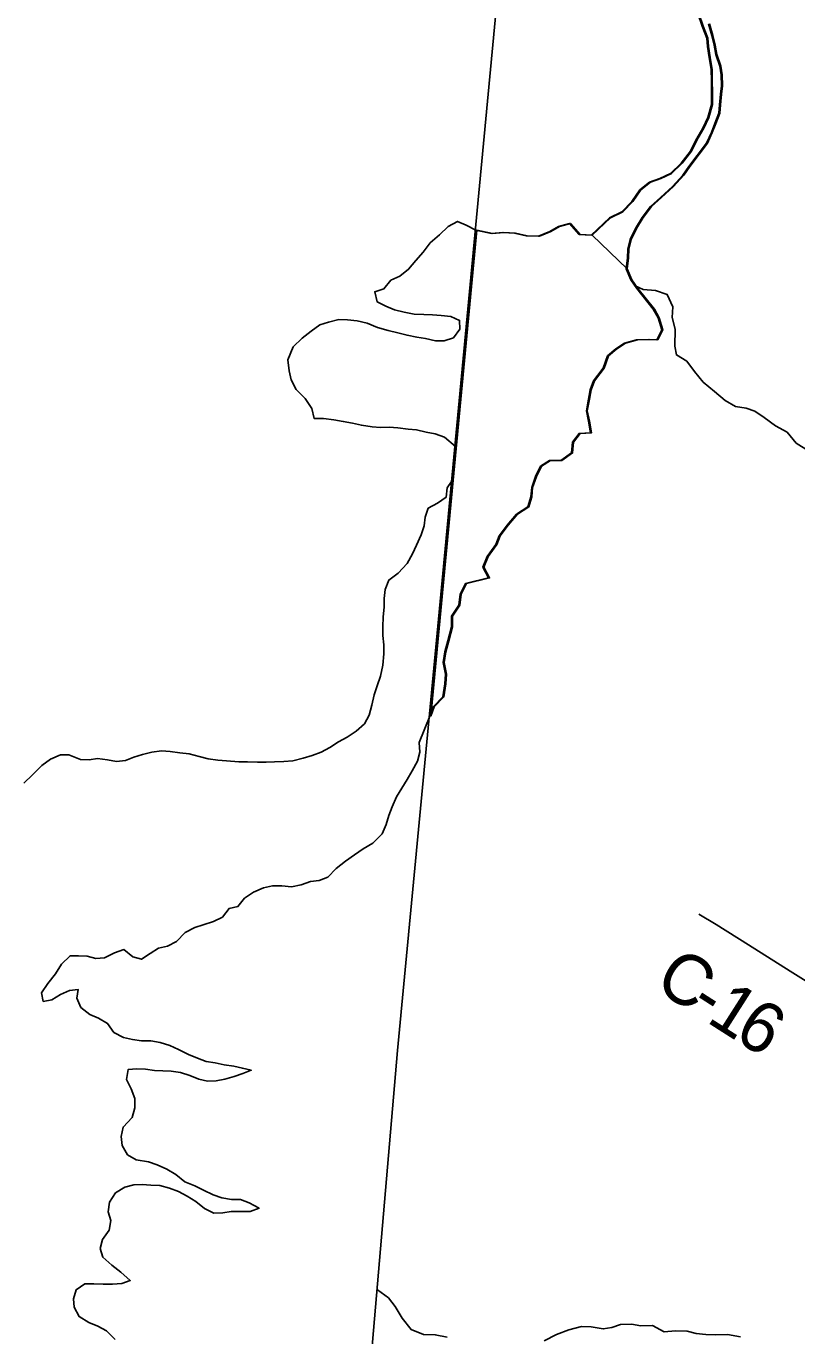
# Model space of a CAD drawing. Extents: x 1442749 to 1756758, y 235267 to 677782.
# Drawn here: x 1548844 to 1553409, y 561298 to 569056 of the extents above; entities that cross this region are included whole.
import ezdxf

# ---------------------------------------------------------------- set-up
doc = ezdxf.new("R2010")
doc.units = 0
for name, color, linetype in [('GM_X_Adjacent_County', 7, 'Continuous'), ('GM_X_County', 7, 'Continuous'), ('GM_X_County_Road', 7, 'Continuous'), ('GM_X_County_Road_Text', 7, 'Continuous'), ('GM_X_Major_Lake', 7, 'Continuous'), ('GM_X_Major_River', 7, 'Continuous'), ('GM_X_Minor_River', 7, 'Continuous'), ('GM_X_Township', 7, 'Continuous')]:
    doc.layers.add(name, color=color, linetype=linetype)

msp = doc.modelspace()

# ---------------------------------------------------------------- linework, layer by layer
at = {"layer": 'GM_X_Adjacent_County'}
msp.add_lwpolyline([(1510501.5, 579143.6), (1513514.2, 578839.9), (1514569.4, 578743.8), (1516950, 578526.9), (1518829.2, 578331.8), (1524308.5, 577745.2), (1526680.1, 577523.9), (1529626.7, 577249.2), (1531676.6, 577058.1), (1536645.4, 576561.3), (1543156.7, 575957.6), (1545678.1, 575724.5), (1546403.2, 575641.6), (1549246.3, 575316.8), (1549693.5, 575265.7), (1552179.9, 574981.5), (1551567.1, 568507.3), (1551312.1, 565815), (1551044.2, 562987.6), (1549909.5, 549764.5)], dxfattribs=at)
at = {"layer": 'GM_X_County'}
msp.add_lwpolyline([(1549909.5, 549764.5), (1551044.2, 562987.6), (1551312.1, 565815), (1551567.1, 568507.3), (1552179.9, 574981.5), (1554998.6, 574736.4), (1559309.5, 574361.4), (1567480, 573617.6), (1572928.5, 573040.3)], dxfattribs=at)
at = {"layer": 'GM_X_County_Road'}
msp.add_lwpolyline([(1552829.3, 563796.3), (1552931.1, 563735.8), (1553122.5, 563615.3), (1553368.7, 563458.6), (1553713.5, 563242.7), (1553882.9, 563136.1), (1554050, 563032.1), (1554178.3, 562952.7), (1554281.9, 562889.8)], dxfattribs=at)
at = {"layer": 'GM_X_Major_Lake'}
for p, q in [((1551235, 564969.3), (1551507.7, 567847.8)), ((1551513.6, 567847.8), (1551240.9, 564969.3)), ((1551386.4, 566567.3), (1551507.7, 567847.8)), ((1552403.3, 567618.9), (1552196.8, 567817.5)), ((1551235, 564969.3), (1551367.3, 566365.7))]:
    msp.add_line(p, q, dxfattribs=at)
for points in [[(1551507.7, 567847.8), (1551450.7, 567878.2), (1551399.1, 567899.6), (1551344.2, 567869), (1551292.7, 567820.2), (1551237.4, 567773.5), (1551195.8, 567718.4), (1551152.4, 567667.4), (1551108.9, 567616.3), (1551057.7, 567575.5), (1551004.9, 567550.9), (1550963.5, 567499.8), (1550908.9, 567483.2), (1550923.3, 567422.6), (1550974.8, 567397.1), (1551026.3, 567375.7), (1551084.1, 567362.1), (1551142, 567350.6), (1551200.1, 567349), (1551250.1, 567345.7), (1551302.2, 567342.3), (1551360.2, 567336.7), (1551411.7, 567313.3), (1551412.3, 567261.1), (1551374.9, 567209.9), (1551320.3, 567193.3), (1551268.1, 567192.7), (1551210.3, 567206.3), (1551158.4, 567213.7), (1551100.6, 567225.2), (1551044.8, 567240.8), (1550989.1, 567254.3), (1550925.4, 567272), (1550863.9, 567297.7), (1550804.1, 567311.4), (1550748.1, 567316.9), (1550696, 567318.2), (1550635.5, 567303.8), (1550582.9, 567287.1), (1550531.8, 567250.4), (1550478.5, 567207.6), (1550425, 567156.9), (1550394.9, 567079.4), (1550401.2, 567015), (1550413.8, 566960.5), (1550444.4, 566903.5), (1550497.1, 566849.9), (1550535.7, 566790.7), (1550550.2, 566732.1), (1550606.3, 566732.7), (1550666.3, 566725), (1550722.2, 566715.5), (1550778, 566704), (1550829.8, 566692.6), (1550893.7, 566682.9), (1550943.8, 566679.5), (1550993.9, 566680.2), (1551046, 566676.8), (1551105.9, 566669.2), (1551156, 566665.9), (1551213.7, 566652.3), (1551267.6, 566640.9), (1551321.2, 566621.4), (1551386.4, 566567.3)], [(1551507.7, 567847.8), (1551599.7, 567829.2), (1551667.9, 567833.9), (1551736, 567830.5), (1551805.9, 567815.1), (1551878, 567811.7), (1551946.7, 567840.4), (1551997.4, 567869.5), (1552061.9, 567888.3), (1552118.8, 567823), (1552190.8, 567817.5)], [(1552196.8, 567817.5), (1552124.7, 567823), (1552067.9, 567888.3), (1552003.3, 567869.5), (1551952.6, 567840.4), (1551883.9, 567811.7), (1551811.8, 567815.1), (1551742, 567830.5), (1551673.9, 567833.9), (1551605.6, 567829.2), (1551513.6, 567847.8)], [(1551235, 564969.3), (1551255.3, 565024.5), (1551312.6, 565083.5), (1551324.1, 565161.5), (1551327.3, 565217.6), (1551314.6, 565286), (1551323.9, 565350), (1551341.2, 565415.8), (1551362.9, 565497.6), (1551364.2, 565561.7), (1551407.6, 565627), (1551414.9, 565691.1), (1551446.2, 565754.6), (1551583.2, 565788), (1551548.3, 565850.8), (1551575.7, 565914.5), (1551625.2, 565985.7), (1551646.3, 566037.4), (1551693.6, 566100.6), (1551749.1, 566165.7), (1551816.1, 566208.5), (1551833.3, 566268.3), (1551838.4, 566324.4), (1551861.7, 566388.1), (1551891, 566449.7), (1551943.8, 566482.7), (1552012, 566483.4), (1552075, 566528.2), (1552080.3, 566592.3), (1552119.4, 566643.7), (1552187.6, 566648.3), (1552175, 566716.8), (1552162.2, 566777.2), (1552175.6, 566847.1), (1552184.7, 566903.1), (1552203.8, 566954.9), (1552261.4, 567029.9), (1552286.9, 567103.6), (1552337.8, 567144.7), (1552388.6, 567177.8), (1552459.2, 567198.5), (1552529.4, 567201.1), (1552579.5, 567198.1), (1552608.7, 567257.7), (1552588.1, 567328.3), (1552559, 567381), (1552461.2, 567503.3), (1552426.2, 567554.1), (1552397.4, 567618.9)], [(1551240.9, 564969.3), (1551261.2, 565024.5), (1551318.5, 565083.5), (1551330.1, 565161.5), (1551333.2, 565217.6), (1551320.5, 565286), (1551329.8, 565350), (1551347.1, 565415.8), (1551368.8, 565497.6), (1551370.1, 565561.7), (1551413.5, 565627), (1551420.8, 565691.1), (1551452.1, 565754.6), (1551589.1, 565788), (1551554.3, 565850.8), (1551581.6, 565914.5), (1551631.1, 565985.7), (1551652.2, 566037.4), (1551699.6, 566100.6), (1551755, 566165.7), (1551822, 566208.5), (1551839.2, 566268.3), (1551844.3, 566324.4), (1551867.7, 566388.1), (1551896.9, 566449.7), (1551949.7, 566482.7), (1552017.9, 566483.4), (1552080.9, 566528.2), (1552086.2, 566592.3), (1552125.3, 566643.7), (1552193.6, 566648.3), (1552180.9, 566716.8), (1552168.1, 566777.2), (1552181.5, 566847.1), (1552190.6, 566903.1), (1552209.7, 566954.9), (1552267.3, 567029.9), (1552292.8, 567103.6), (1552343.8, 567144.7), (1552394.5, 567177.8), (1552465.1, 567198.5), (1552535.3, 567201.1), (1552585.4, 567198.1), (1552614.6, 567257.7), (1552594, 567328.3), (1552565, 567381), (1552467.2, 567503.3), (1552432.1, 567554.1), (1552403.3, 567618.9)], [(1551367.3, 566365.7), (1551337.3, 566322), (1551331.9, 566265.9), (1551280.8, 566231.2), (1551225.9, 566200.5), (1551208.4, 566148.8), (1551201.1, 566096.8), (1551183.6, 566043.1), (1551155.9, 565981.6), (1551132.5, 565930.1), (1551100.9, 565872.7), (1551047.3, 565816), (1550992, 565775.3), (1550970.5, 565719.7), (1550965.1, 565665.7), (1550963.8, 565615.5), (1550958.2, 565557.5), (1550956.6, 565497.3), (1550957.3, 565447.2), (1550961.8, 565390.8), (1550962.4, 565338.7), (1550956.6, 565270.6), (1550942.9, 565206.8), (1550923.4, 565149.1), (1550905.9, 565095.4), (1550892.2, 565033.5)], [(1550892.2, 565033.5), (1550876.7, 564975.8), (1550849.2, 564924.3), (1550797.9, 564879.5), (1550744.9, 564844.8), (1550694, 564816.1), (1550643, 564783.3), (1550592.2, 564756.6), (1550537.5, 564736), (1550484.9, 564719.3), (1550424.4, 564704.9), (1550370.1, 564700.3), (1550315.9, 564697.7), (1550265.7, 564697.1), (1550213.6, 564696.4), (1550155.5, 564698), (1550103.4, 564699.4), (1550031.4, 564705.3), (1549979.3, 564708.7), (1549921.4, 564716.2), (1549869.6, 564729.6), (1549809.9, 564745.3), (1549753.9, 564752.8), (1549698, 564760.3), (1549645.9, 564763.7), (1549587.6, 564755.2), (1549533.1, 564742.6), (1549482.5, 564725.9), (1549431.9, 564707.2), (1549379.6, 564700.5), (1549325.7, 564710), (1549267.7, 564717.5), (1549217.4, 564710.8), (1549165.3, 564712.2), (1549097.9, 564740.1), (1549047.8, 564739.4), (1548989, 564714.9), (1548937.8, 564676.1), (1548882.2, 564621.4), (1548830.8, 564572.6)], [(1549444.2, 562369.5), (1549413.6, 562426.5), (1549407, 562478.8), (1549418.5, 562534.7), (1549472.1, 562591.5), (1549487.7, 562649.2), (1549487.1, 562703.4), (1549466.6, 562762.1), (1549438, 562817.1), (1549447.6, 562875), (1549499.8, 562879.6), (1549551.9, 562878.2), (1549603.9, 562870.8), (1549653.9, 562867.5), (1549704, 562866.2), (1549757.9, 562858.7), (1549813.6, 562841.2), (1549867.2, 562819.7), (1549919, 562806.3), (1549969.2, 562809), (1550021.6, 562819.6), (1550076.1, 562834.2), (1550126.7, 562852.9), (1550177.3, 562871.7), (1550125.5, 562883.1), (1550073.7, 562896.5), (1550017.8, 562904), (1549964, 562915.4), (1549910, 562922.9), (1549858.4, 562942.3), (1549804.9, 562965.8), (1549747.5, 562995.4), (1549696, 563018.9), (1549638.3, 563036.4), (1549582.4, 563045.9), (1549528.3, 563045.4), (1549474.3, 563052.8), (1549420.5, 563066.3), (1549363.2, 563095.9), (1549326.5, 563149), (1549273.2, 563180.6), (1549221.6, 563202), (1549168.6, 563243.5), (1549144, 563298.3), (1549151.4, 563350.3), (1549101.1, 563343.6), (1549048.3, 563320.9), (1548995.3, 563288.2), (1548945, 563279.6), (1548934.3, 563330), (1548971.8, 563385.2), (1549017.4, 563442.2), (1549053.1, 563499.4), (1549104.5, 563550.2), (1549154.6, 563548.8), (1549204.7, 563547.5), (1549256.5, 563534.1), (1549308.7, 563536.7), (1549367.6, 563567.3), (1549422.3, 563585.9), (1549475.3, 563544.3), (1549527, 563528.9), (1549578.1, 563563.7), (1549629, 563594.4), (1549681.5, 563607.1), (1549734.3, 563633.8), (1549785.9, 563686.6), (1549842.8, 563717.2), (1549893.4, 563733.9), (1549954, 563752.3), (1550006.9, 563779), (1550046.3, 563830.1), (1550098.7, 563840.8), (1550138.2, 563891.9), (1550191.2, 563926.6), (1550250.1, 563953.1), (1550302.5, 563963.8), (1550358.6, 563964.3), (1550416.6, 563958.7), (1550473.1, 563969.3), (1550527.8, 563989.9), (1550580.1, 563996.5), (1550630.7, 564015.2), (1550680.2, 564066.1), (1550735.5, 564110.8), (1550788.6, 564147.5), (1550839.6, 564182.2), (1550896.7, 564216.8), (1550952.3, 564271.5), (1550975.8, 564327.1), (1550993.3, 564380.8), (1551012.7, 564432.4), (1551038.3, 564491.9), (1551069.7, 564543.3), (1551101.2, 564594.6), (1551130.6, 564646), (1551162.2, 564703.3), (1551175.6, 564755.2), (1551171.1, 564813.5), (1551235, 564969.3)], [(1549371.2, 561276.1), (1549320.4, 561327.6), (1549269, 561355), (1549215.4, 561376.5), (1549158.2, 561412.1), (1549127.6, 561467.1), (1549124.9, 561517.3), (1549140.4, 561571.1), (1549191.4, 561605.9), (1549245.6, 561606.4), (1549299.7, 561605), (1549355.8, 561603.5), (1549410, 561608.1), (1549460.6, 561626.8), (1549405.8, 561676.4), (1549350.7, 561716), (1549297.8, 561763.5), (1549283.2, 561816.1), (1549296.6, 561869.9), (1549336.2, 561925), (1549345.7, 561980.9), (1549329.1, 562033.5), (1549338.6, 562089.4), (1549374.1, 562144.7), (1549429.2, 562179.3), (1549481.6, 562192), (1549531.8, 562194.7), (1549581.9, 562191.3), (1549635.9, 562187.9), (1549693.6, 562172.3), (1549747.3, 562152.8), (1549798.7, 562125.4), (1549850, 562093.9), (1549901, 562052.4), (1549956.4, 562024.9), (1550008.6, 562027.5), (1550058.9, 562034.2), (1550119.1, 562034.6), (1550171.2, 562035.2), (1550223.9, 562053.9), (1550164.5, 562085.6), (1550112.9, 562105), (1550060.8, 562106.4), (1550002.9, 562115.9), (1549951.3, 562133.3), (1549893.8, 562161), (1549842.4, 562186.4), (1549784.9, 562210), (1549729.9, 562253.6), (1549676.6, 562285.1), (1549621.1, 562310.7), (1549569.4, 562328.1), (1549495.6, 562340.1), (1549444.2, 562369.5)]]:
    msp.add_lwpolyline(points, dxfattribs=at)
at = {"layer": 'GM_X_Major_River'}
msp.add_line((1552403.3, 567618.9), (1552196.8, 567817.5), dxfattribs=at)
for points in [[(1552190.8, 567817.5), (1552299.2, 567921.7), (1552372, 567956.3), (1552431.4, 568017.3), (1552478.8, 568086.6), (1552535.9, 568131.6), (1552598.5, 568154.4), (1552661.2, 568183.3), (1552724.5, 568244.2), (1552780.1, 568315.3), (1552811.4, 568380.9), (1552853, 568452.2), (1552882.3, 568515.8), (1552903.8, 568591.7), (1552903.3, 568665.9), (1552902.6, 568732.1), (1552902, 568800.3), (1552889.3, 568870.8), (1552880.6, 568935.1), (1552875.6, 568985.4), (1552848.9, 569056.1), (1552822.3, 569130.8)], [(1552196.8, 567817.5), (1552305.1, 567921.7), (1552377.9, 567956.3), (1552437.3, 568017.3), (1552484.8, 568086.6), (1552541.8, 568131.6), (1552604.4, 568154.4), (1552667.1, 568183.3), (1552730.5, 568244.2), (1552786, 568315.3), (1552817.4, 568380.9), (1552858.9, 568452.2), (1552888.2, 568515.8), (1552909.8, 568591.7), (1552909.2, 568665.9), (1552908.5, 568732.1), (1552907.9, 568800.3), (1552895.3, 568870.8), (1552886.5, 568935.1), (1552881.5, 568985.4), (1552854.8, 569056.1), (1552828.2, 569130.8)], [(1552397.4, 567618.9), (1552406.7, 567684.9), (1552407.7, 567735), (1552420.9, 567792.9), (1552454.3, 567858.4), (1552493.6, 567923.8), (1552543.1, 567989), (1552602.2, 568042), (1552671.7, 568106.8), (1552733.2, 568173.8), (1552770.3, 568225.2), (1552873.2, 568363.6), (1552902.6, 568427.2), (1552923.7, 568480.9), (1552946.9, 568540.6), (1552951.9, 568590.7), (1552957.2, 568652.8), (1552962.2, 568702.8), (1552961.5, 568769), (1552952.5, 568819.3), (1552929.8, 568888), (1552918.8, 568944.4), (1552905.9, 569000.8), (1552885.2, 569069.4)], [(1552891.2, 569069.4), (1552911.9, 569000.8), (1552924.8, 568944.4), (1552935.7, 568888), (1552958.4, 568819.3), (1552967.4, 568769), (1552968.1, 568702.8), (1552963.1, 568652.8), (1552957.8, 568590.7), (1552952.8, 568540.7), (1552929.6, 568480.9), (1552908.5, 568427.2), (1552879.2, 568363.6), (1552776.2, 568225.2), (1552739.1, 568173.8), (1552677.6, 568106.8), (1552608.2, 568042), (1552549, 567989), (1552499.6, 567923.8), (1552460.2, 567858.4), (1552426.8, 567792.9), (1552413.6, 567735), (1552412.6, 567684.9), (1552403.3, 567618.9)]]:
    msp.add_lwpolyline(points, dxfattribs=at)
at = {"layer": 'GM_X_Minor_River'}
for points in [[(1552450.9, 567518.2), (1552499.2, 567496.5), (1552571.3, 567491.1), (1552641, 567467.6), (1552673.6, 567394.8), (1552670.3, 567330.7), (1552689, 567262.1), (1552687, 567159.9), (1552696, 567109.5), (1552757.4, 567072.2), (1552802.3, 567011.2), (1552855.1, 566948), (1552922.2, 566892.5), (1552985.3, 566839.1), (1553046.7, 566803.8), (1553108.7, 566794.5), (1553160.4, 566775.4), (1553215.8, 566738.3), (1553283, 566688.8), (1553352.4, 566651.3), (1553405.3, 566586.1), (1553478.5, 566540.5)], [(1550925.7, 561571.5), (1550991.1, 561522.9), (1551030.2, 561472), (1551070.9, 561403), (1551123.7, 561335.8), (1551197.3, 561306.3), (1551267.4, 561304.9), (1551337.3, 561289.4)], [(1551912.2, 561268), (1551985.1, 561306.7), (1552057.8, 561333.3), (1552134.4, 561353.8), (1552190.5, 561350.7), (1552262.4, 561339.2), (1552312.7, 561348.3), (1552365.2, 561365.3), (1552431.4, 561368), (1552483.3, 561356.9), (1552553.5, 561359.5), (1552622.9, 561322), (1552691.2, 561328.7), (1552759.3, 561325.4), (1552813.2, 561312.2), (1552869.2, 561307.1), (1552929.3, 561303.9), (1552997.5, 561306.6), (1553075.4, 561293)]]:
    msp.add_lwpolyline(points, dxfattribs=at)
at = {"layer": 'GM_X_Township'}
msp.add_lwpolyline([(1574567.9, 539458.5), (1566007.1, 539894.4), (1561723.7, 540198.8), (1558042.4, 540322.3), (1554905.7, 540487.3), (1549399.3, 540776.8), (1549067.9, 540794.2), (1549410.8, 544569.8), (1549796.7, 548590.4), (1549909.5, 549764.5), (1551044.2, 562987.6), (1551312.1, 565815), (1551567.1, 568507.3), (1552179.9, 574981.5), (1554998.6, 574736.4), (1559309.5, 574361.4), (1567480, 573617.6), (1572928.5, 573040.3)], dxfattribs=at)

# ---------------------------------------------------------------- texts
at = {"layer": 'GM_X_County_Road_Text'}
for s, rotation, p in [('C', 327.20087, (1552554, 563363)), ('-', 327.25447, (1552761.4, 563229.3)), ('1', 327.46223, (1552866, 563162.1)), ('6', 328.51597, (1553026.9, 563059.5))]:
    msp.add_text(s, height=300, rotation=rotation, dxfattribs=at).set_placement(p)

doc.saveas('drawing.dxf')
